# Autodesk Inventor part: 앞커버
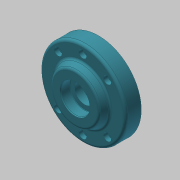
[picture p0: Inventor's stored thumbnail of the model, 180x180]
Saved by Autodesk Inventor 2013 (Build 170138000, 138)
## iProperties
Company: 한국ATC센터
Created: 2015-12
Part Number: 앞커버
Document SubType Name: Modeling
Designer: 앞커버
Density: 2.71 g/cm^3
Mass: 113.475 g
Surface Area: 120.821 cm^2
Volume: 41.8727 cm^3
Material: 알루미늄 6061
Author: mdu
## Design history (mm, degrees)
sketch "스케치1"
  geometry: L1 (-11.5, 0)-(11.5, 0); L2 (11.5, 0)-(11.5, 22.5); L3 (11.5, 22.5)-(6.5, 22.5); L4 (6.5, 22.5)-(6.5, 32.5); L5 (6.5, 32.5)-(-5.5, 32.5); L6 (-5.5, 32.5)-(-5.5, 21); L7 (-5.5, 21)-(-11.5, 18.202); L8 (-11.5, 18.202)-(-11.5, 0); 2 further points
  constraints: 16 end point, 3 parallel, 3 perpendicular, 1 coincident, 1 horizontal, 1 midpoint
  dimensions: "d0" = 23 distance of L1.start L1.end; "d1" = 65 diameter of L5 L1; "d2" = 45 diameter of L3 L1; "d3" = 42 diameter of L6.end L1; "d4" = 115 deg angle of L7 L6; "d5" = 12 distance of L4.end L5.end; "d6" = 5 distance of L2.end L3.end
revolve "회전1" sketch "스케치1" stored, may be unused: angle "d7" = 90 deg
sketch "스케치2"
  geometry: L1 (0, 0)-(32.5, 0); L2 (0, 0)-(0, 26.5); 1 further point
  constraints: 4 end point, 1 horizontal, 1 horizontal alignment, 1 other
  dimensions: "d8" = 90 deg angle of L1 L2; "d9" = 26.5 distance of L1.start L2.end
hole "구멍1" sketch "스케치2" at (0, 26.5) diameter "d10" = 3.4; stored, may be unused: countersink angle "d14" = 90 deg, drill point angle "d16" = 118 deg; dims "d11" = 6, "d12" = 6, "d13" = 3.3, "d15" = 8
fillet "모깎기1" dims "d20" = 2
hole "구멍2" diameter "d23" = 15; stored, may be unused: countersink angle "d27" = 90 deg, drill point angle "d29" = 118 deg; dims "d21" = 10, "d22" = 10, "d24" = 6, "d25" = 32, "d26" = 10, "d28" = 8
hole "구멍3" diameter "d32" = 22; stored, may be unused: countersink angle "d36" = 90 deg, drill point angle "d38" = 0 deg; dims "d33" = 6, "d34" = 32, "d35" = 10, "d37" = 7.3, "d46" = 10, "d47" = 10
chamfer "모따기1" distance "d39" = 1; stored, may be unused: second distance "d40" = 2, angle "d41" = 45 deg
chamfer "모따기2" distance "d43" = 0.7; stored, may be unused: second distance "d44" = 2, angle "d45" = 30 deg
fillet "모깎기2" dims "d42" = 0.3
node "솔리드1"
pattern_circular "원형 패턴1" dims angle "d18" = 360 deg
